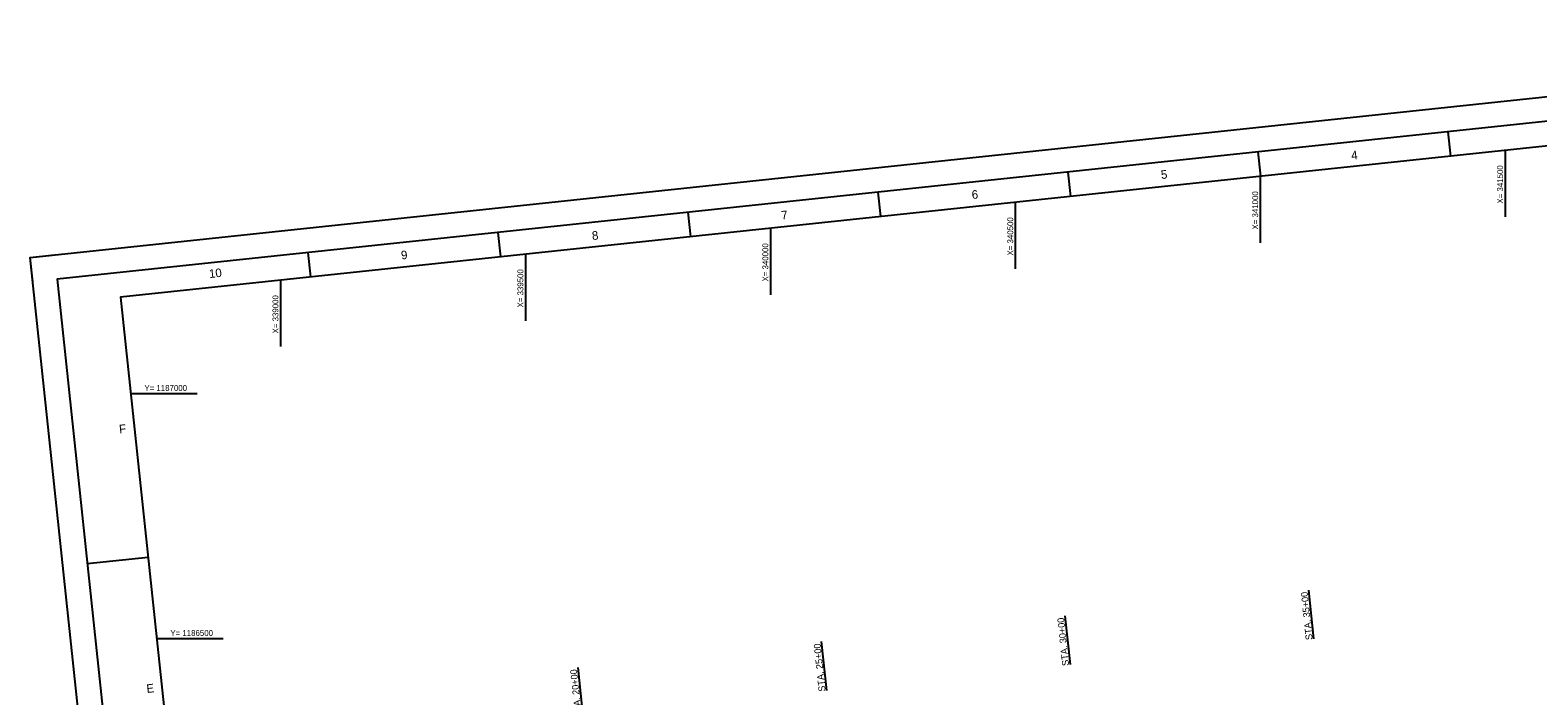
# Model space of a CAD drawing. Extents: x 338488 to 343222, y 1183896 to 1187741.
# Drawn here: x 338488 to 341566, y 1186383 to 1187741 of the extents above; entities that cross this region are included whole.
import ezdxf

# ---------------------------------------------------------------- set-up
doc = ezdxf.new("R2010")
doc.units = 0
for name, color, linetype in [('G-ANNO-NPLT', 7, 'Continuous'), ('G-ANNO-TTLB', 7, 'Continuous'), ('V-ALGN-TEXT', 7, 'Continuous'), ('V-TOPO-COOR-STAT', 7, 'Continuous')]:
    doc.layers.add(name, color=color, linetype=linetype)

msp = doc.modelspace()

# ---------------------------------------------------------------- linework, layer by layer
at = {"layer": 'G-ANNO-NPLT'}
msp.add_lwpolyline([(338488.3, 1187277.4), (342863.7, 1187741.2), (343222.1, 1184360.2), (338846.6, 1183896.4)], close=True, dxfattribs=at)
msp.add_lwpolyline([(338493.5, 1187227.7), (338488.3, 1187277.4), (338538, 1187282.7)], dxfattribs=at)
at = {"layer": 'G-ANNO-TTLB'}
for p, q in [((341382.3, 1187533.9), (341387.6, 1187484.2)), ((340994.5, 1187492.8), (340999.8, 1187443.1)), ((340606.7, 1187451.7), (340612, 1187402)), ((340218.9, 1187410.6), (340224.1, 1187360.9)), ((339831, 1187369.5), (339836.3, 1187319.8)), ((339443.2, 1187328.4), (339448.5, 1187278.7)), ((339443.2, 1187328.4), (339448.5, 1187278.7)), ((339055.4, 1187287.3), (339060.7, 1187237.6)), ((338604.8, 1186652.7), (338729.1, 1186665.9))]:
    msp.add_line(p, q, dxfattribs=at)
for points in [[(338891.1, 1183951.4), (343167.1, 1184404.6), (342819.3, 1187686.2), (338543.3, 1187233)], [(342774.8, 1187631.3), (338672.8, 1187196.4), (339010.1, 1184014.3), (343112.1, 1184449.1)]]:
    msp.add_lwpolyline(points, close=True, dxfattribs=at)
at = {"layer": 'V-ALGN-TEXT'}
for p, q in [((341108.9, 1186499.4), (341098.4, 1186598.8)), ((340611.7, 1186446.7), (340601.1, 1186546.1)), ((340114.5, 1186393.9), (340103.9, 1186493.4)), ((339617.3, 1186341.2), (339606.7, 1186440.7))]:
    msp.add_line(p, q, dxfattribs=at)
at = {"layer": 'V-TOPO-COOR-STAT'}
for p, q in [((341500, 1187360.4), (341500, 1187496.1)), ((341000, 1187307.4), (341000, 1187443.1)), ((340500, 1187254.4), (340500, 1187390.1)), ((340000, 1187201.4), (340000, 1187337.1)), ((339500, 1187148.4), (339500, 1187284.1)), ((339000, 1187095.4), (339000, 1187231.1)), ((338693.7, 1187000), (338829.4, 1187000)), ((338746.6, 1186500), (338882.4, 1186500))]:
    msp.add_line(p, q, dxfattribs=at)

# ---------------------------------------------------------------- texts
at = {"layer": 'G-ANNO-TTLB'}
for s, p in [('4', (341185.9, 1187476.8)), ('5', (340797.5, 1187437.4)), ('6', (340411.2, 1187396.5)), ('7', (340022.5, 1187354.6)), ('8', (339636, 1187312.9)), ('9', (339246.3, 1187273.2)), ('10', (338854.3, 1187235.3)), ('F', (338670.7, 1186918.3)), ('E', (338726.7, 1186388.6))]:
    msp.add_text(s, height=17.5, rotation=6.0506, dxfattribs=at).set_placement(p)
at = {"layer": 'V-ALGN-TEXT'}
for s, p in [('STA. 35+00', (341106.3, 1186497.4)), ('STA. 30+00', (340609.1, 1186444.7)), ('STA. 25+00', (340111.9, 1186392)), ('STA. 20+00', (339614.7, 1186339.3))]:
    msp.add_text(s, height=13.92, rotation=96.0506, dxfattribs=at).set_placement(p)
at = {"layer": 'V-TOPO-COOR-STAT'}
for s, p in [('X= 341500', (341495, 1187387.4)), ('X= 341000', (340995, 1187334.4)), ('X= 340500', (340495, 1187281.4)), ('X= 340000', (339995, 1187228.4)), ('X= 339500', (339495, 1187175.4)), ('X= 339000', (338995, 1187122.4))]:
    msp.add_text(s, height=12, rotation=90, dxfattribs=at).set_placement(p)
for s, p in [('Y= 1187000', (338721.5, 1187005)), ('Y= 1186500', (338774.5, 1186505))]:
    msp.add_text(s, height=12, dxfattribs=at).set_placement(p)

doc.saveas('drawing.dxf')
